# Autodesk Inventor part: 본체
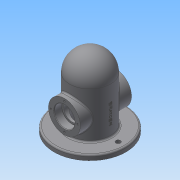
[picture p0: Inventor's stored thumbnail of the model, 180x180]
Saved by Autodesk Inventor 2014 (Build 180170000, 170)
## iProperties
Created: 2019-11
Part Number: 본체
Material: 일반
Document SubType Name: Modeling
Designer: net
Density: 1 g/cm^3
Appearance: 기본값
Author: net
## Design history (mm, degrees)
sketch "스케치1"
  geometry: C1 r 70 at (0, 0); 1 further point
  constraints: 1 centre point, 1 coincident
  dimensions: "d0" = 140 diameter of C1
extrude "돌출1" new body sketch "스케치1" distance "d1" = 10; taper "d2" = 0 deg
sketch "스케치2"
  geometry: C1 r 70 at (0, 0) reference; C2 r 40 at (0, 0)
  constraints: 1 centre point, 1 coincident
  dimensions: "d3" = 80 diameter of C2
extrude "돌출2" join sketch "스케치2" distance "d4" = 90; taper "d5" = 0 deg
sketch "스케치3"
  geometry: L1 (-70, 0)-(-70, 10) reference; L2 (-70, 10)-(-40, 10) reference; L3 (-40, 10)-(-40, 100) reference; L4 (-40, 100)-(40, 100) reference; L5 (40, 100)-(40, 10) reference; L6 (40, 10)-(70, 10) reference; L7 (70, 10)-(70, 0) reference; L8 (70, 0)-(-70, 0) reference; L9 (0, 100)-(0, 140); L10 (0, 100)-(0, 140); L11 (0, 100)-(40, 100); A1 r 40 centre (0, 100) between (40, 100) and (0, 140); 1 further point
  constraints: 6 end point, 2 perpendicular, 2 point on circle, 1 centre point, 1 coincident, 1 collinear, 1 midpoint
  dimensions: "d6" = 40 distance of L9.start L9.end
revolve "회전1" sketch "스케치3" stored, may be unused: angle "d7" = 90 deg
feature "쉘1" dims "d16" = 10
node "작업 평면1"
sketch "스케치4"
  geometry: L1 (40, 100)-(-40, 100) reference; L2 (-40, 10)-(40, 10) reference; L3 (-70, 0)-(70, 0) reference; C1 r 31 at (0, 50); 2 further points
  constraints: 1 centre point, 1 midpoint, 1 vertical alignment
  dimensions: "d9" = 62 diameter of C1; "d10" = 50 distance from line of L3 C1.centre
extrude "돌출3" join sketch "스케치4" stored distance "d11" = 90; taper "d12" = 0 deg
sketch "스케치5"
  geometry: C1 r 31 at (0, 0) reference; C2 r 20 at (0, 0); 1 further point
  constraints: 1 centre point, 1 coincident
  dimensions: "d13" = 40 diameter of C2
extrude "돌출4" cut sketch "스케치5" distance "d14" = 15; taper "d15" = 0 deg
sketch "스케치6"
  geometry: C1 r 20 at (0, 0) reference; C2 r 16.5 at (0, 0); 1 further point
  constraints: 1 centre point, 1 coincident
  dimensions: "d17" = 33 diameter of C2
extrude "돌출5" cut sketch "스케치6" distance "d18" = 34.75; taper "d19" = 0 deg
sketch "스케치7"
  geometry: C1 r 31 at (0, 0) reference; C2 r 20 at (0, 0); 1 further point
  constraints: 1 centre point, 1 coincident
  dimensions: "d20" = 40 diameter of C2
extrude "돌출6" cut sketch "스케치7" distance "d21" = 15; taper "d22" = 0 deg
sketch "스케치8"
  geometry: C1 r 20 at (0, 0) reference; C2 r 16.5 at (0, 0); 1 further point
  constraints: 1 centre point, 1 coincident
  dimensions: "d23" = 33 diameter of C2
extrude "돌출7" cut sketch "스케치8" distance "d24" = 15; taper "d25" = 0 deg
sketch "스케치9" dims "d26" = 52
  geometry: C1 r 20 at (0, 0) reference; 3 further points
  constraints: 2 vertical alignment, 1 coincident, 2 other
hole "구멍1" sketch "스케치9" at (0, -26) diameter "d27" = 3.242; stored, may be unused: countersink angle "d31" = 82 deg, drill point angle "d33" = 118 deg; dims "d28" = 8, "d29" = 3.023, "d30" = 2, "d32" = 10
sketch "스케치10" dims "d37" = 52
  geometry: C1 r 31 at (0, 0) reference; 3 further points
  constraints: 2 vertical alignment, 1 coincident, 2 other
hole "구멍2" sketch "스케치10" at (0, 26) diameter "d38" = 3.242; stored, may be unused: countersink angle "d42" = 82 deg, drill point angle "d44" = 118 deg; dims "d39" = 8, "d40" = 3.023, "d41" = 2, "d43" = 10
node "작업 평면3"
sketch "스케치11"
  geometry: C1 r 40 at (0, 0) reference; C2 r 7.5 at (0, 0); 1 further point
  constraints: 1 centre point, 1 coincident
  dimensions: "d49" = 15 diameter of C2
extrude "돌출8" join sketch "스케치11" stored distance "d50" = 15; taper "d51" = 0 deg
sketch "스케치12"
  geometry: C1 r 7.5 at (0, 0) reference; 1 further point
  constraints: 1 coincident
hole "구멍3" sketch "스케치12" at (0, 0) diameter "d52" = 5.188; stored, may be unused: countersink angle "d56" = 82 deg, drill point angle "d58" = 118 deg; dims "d53" = 33, "d54" = 3.023, "d55" = 2, "d57" = 33.75
sketch "스케치13"
  geometry: C1 r 40 at (0, 0) reference; C2 r 4.5 at (55, 0); C3 r 4.5 at (-55, 0)
  constraints: 2 centre point, 2 horizontal alignment
  dimensions: "d59" = 9 diameter of C2; "d60" = 9 diameter of C3; "d61" = 55 distance of C1.centre C3.centre; "d62" = 55 distance of C1.centre C2.centre
extrude "돌출9" cut sketch "스케치13" distance "d63" = 15; taper "d64" = 0 deg
node "작업 평면4"
sketch "스케치14"
  geometry: L1 (-70, 0)-(70, 0) reference; 3 further points
  constraints: 1 midpoint, 1 vertical alignment, 1 other
  dimensions: "d67" = 50 distance of point (0, 0) point (0, 50)
feature "엠보싱1" sketch "스케치14" dims "d2" = 0, "d68" = 0.5, "d69" = 0
fillet "모깎기1" dims "d70" = 0.3
fillet "모깎기2" dims "d71" = 3
chamfer "모따기1" distance "d72" = 1; stored, may be unused: second distance "d73" = 2, angle "d74" = 45 deg
chamfer "모따기2" distance "d75" = 1; stored, may be unused: second distance "d76" = 2, angle "d77" = 45 deg
node "솔리드1"
mirror "대칭1"
pattern_circular "원형 패턴1" dims angle "d35" = 360 deg
pattern_circular "원형 패턴2" dims angle "d46" = 360 deg
node "투영된 루프1"
node "작업 평면2"
node "투영된 루프2"
node "절단 모서리 투영1"
other parameters: "d48" = -135
